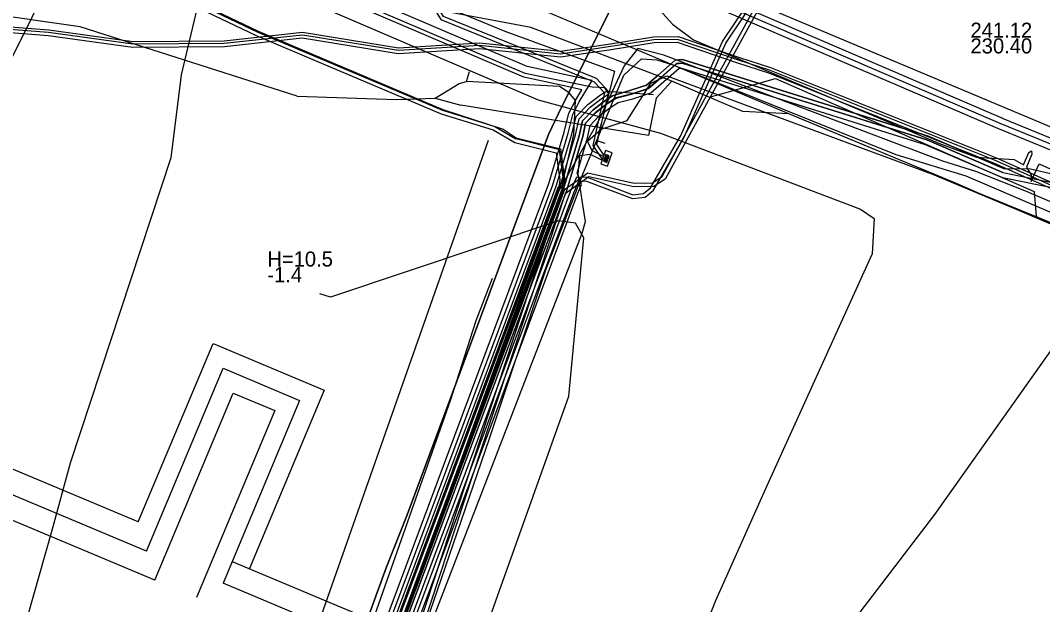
# Model space of a CAD drawing. Extents: x -596024 to -594475, y -1163820 to -1161957.
# Drawn here: x -594948.5 to -594894.3, y -1162166 to -1162135 of the extents above; entities that cross this region are included whole.
import ezdxf

# ---------------------------------------------------------------- set-up
doc = ezdxf.new("R2010")
doc.units = 0
for name, color, linetype in [('Vrstva 10', 7, 'Continuous'), ('Vrstva 12', 7, 'Continuous'), ('Vrstva 13', 7, 'Continuous'), ('Vrstva 19', 7, 'Continuous'), ('Vrstva 28', 7, 'Continuous'), ('Vrstva 29', 7, 'Continuous'), ('Vrstva 30', 7, 'Continuous'), ('Vrstva 32', 7, 'Continuous'), ('Vrstva 42', 7, 'Continuous'), ('Vrstva 43', 7, 'Continuous'), ('Vrstva 44', 7, 'Continuous'), ('Vrstva 55', 7, 'Continuous'), ('Vrstva 58', 7, 'Continuous'), ('Vrstva 9', 7, 'Continuous')]:
    doc.layers.add(name, color=color, linetype=linetype)

# ---------------------------------------------------------------- blocks, each defined once
blk = doc.blocks.new('NN620')
at = {"layer": 'Vrstva 28'}
for points in [[(0.752, 0.004), (-0.748, 0.004)], [(-0.748, 0.004), (-0.748, -0.746)], [(0.752, -0.746), (0.752, 0.004)], [(-0.748, -0.746), (0.752, -0.746)], [(0.368, -0.18), (-0.376, -0.18)], [(-0.376, -0.18), (-0.376, -0.558)], [(-0.376, -0.558), (0.368, -0.558)], [(0.321, -0.227), (-0.329, -0.227)], [(-0.329, -0.227), (-0.329, -0.51)], [(-0.329, -0.51), (0.321, -0.51)], [(0.274, -0.274), (-0.281, -0.274)], [(-0.281, -0.274), (-0.281, -0.463)], [(-0.281, -0.463), (0.274, -0.463)], [(0.227, -0.321), (-0.234, -0.321)], [(-0.234, -0.321), (-0.234, -0.416)], [(-0.234, -0.416), (0.227, -0.416)], [(-0.193, -0.369), (0.185, -0.369)], [(0.227, -0.416), (0.227, -0.321)], [(0.274, -0.463), (0.274, -0.274)], [(0.321, -0.51), (0.321, -0.227)], [(0.368, -0.558), (0.368, -0.18)]]:
    blk.add_lwpolyline(points, dxfattribs=at)

msp = doc.modelspace()

# ---------------------------------------------------------------- linework, layer by layer
at = {"layer": 'Vrstva 10'}
for p, q in [((-594919.937, -1162143.833), (-594940.567, -1162199.07)), ((-594919.582, -1162143.966), (-594919.937, -1162143.833)), ((-594940.222, -1162199.228), (-594919.582, -1162143.966))]:
    msp.add_line(p, q, dxfattribs=at)
for points in [[(-594940.233, -1162121.484), (-594916.901, -1162131.369), (-594896.381, -1162140.194)], [(-594896.619, -1162140.746), (-594917.137, -1162131.921), (-594940.467, -1162122.036)], [(-594896.386, -1162140.192), (-594890.529, -1162142.591), (-594841.464, -1162163.403), (-594840.002, -1162164.043)], [(-594840.243, -1162164.592), (-594841.702, -1162163.954), (-594890.76, -1162143.145), (-594896.614, -1162140.748)]]:
    msp.add_lwpolyline(points, dxfattribs=at)
at = {"layer": 'Vrstva 12'}
for points in [[(-594940.94, -1162120.86), (-594854.77, -1162157.03), (-594809.16, -1162176.45), (-594767.38, -1162194.31)], [(-594911.16, -1162139.42), (-594913.92, -1162138.24), (-594921.4, -1162135.39), (-594927.24, -1162134.29), (-594932.63, -1162132.4), (-594937.89, -1162129.44), (-594940.81, -1162128.13), (-594942.02, -1162127.63), (-594943.32, -1162126.88)], [(-594890.15, -1162147.05), (-594893.45, -1162145.88), (-594897.64, -1162144.17), (-594898.91, -1162143.62), (-594907.38, -1162140.1), (-594931.56, -1162129.92)], [(-594945.29, -1162135.36), (-594970.72, -1162131.69)], [(-594938.65, -1162132.45), (-594939.94, -1162137.9), (-594940.48, -1162142.29), (-594945.83, -1162158.49), (-594946.79, -1162162.06), (-594950.07, -1162173.52), (-594957.82, -1162196.23), (-594973.83, -1162243.01), (-594986.34, -1162280.9), (-594995.28, -1162307.97), (-595001.11, -1162334.64), (-595000.94, -1162335.11), (-594999.28, -1162352.34), (-594997.66, -1162363.83), (-594996.8, -1162372.69), (-594994.36, -1162396.57), (-594993.55, -1162422.69), (-594989.89, -1162471.94), (-594989.27, -1162484.26), (-594988.21, -1162493.1)], [(-594938.18, -1162132.1), (-594937.46, -1162132.16), (-594921, -1162139.23), (-594914.51, -1162140.99), (-594903.91, -1162145.02), (-594903.18, -1162145.52), (-594903.29, -1162147.39), (-594908.88, -1162159.69), (-594911.61, -1162165.81), (-594913.37, -1162170.27), (-594915.79, -1162175.82), (-594916.73, -1162178.42), (-594917.54, -1162180.59), (-594921.54, -1162194.47), (-594922.15, -1162196.85), (-594922.34, -1162197.5), (-594928.73, -1162215.2), (-594934.96, -1162232.34), (-594941.42, -1162249.91), (-594947.63, -1162267.23)], [(-594933.78, -1162139.03), (-594945.29, -1162135.36)], [(-594924.805, -1162138.245), (-594924.64, -1162137.73)], [(-594926.46, -1162139.13), (-594925.2, -1162138.36), (-594924.805, -1162138.245)], [(-594919.76, -1162143.9), (-594919.12, -1162141.06), (-594919.03, -1162139.26), (-594919.36, -1162138.86), (-594919.88, -1162138.52), (-594924.805, -1162138.245)], [(-594913.92, -1162138.24), (-594914.74, -1162139.13), (-594915.15, -1162141.12)], [(-594910.9, -1162138.8), (-594908.41, -1162138.1), (-594894.7, -1162144.09), (-594894.59, -1162145.41), (-594893.45, -1162145.88)], [(-594911.93, -1162139.09), (-594910.9, -1162138.8)], [(-594933.78, -1162139.03), (-594928.51, -1162139.2)], [(-594928.51, -1162139.2), (-594926.46, -1162139.13)], [(-594926.46, -1162139.13), (-594925.1, -1162139.5)], [(-594915.15, -1162141.12), (-594925.1, -1162139.5)], [(-594893.69, -1162145.86), (-594897.64, -1162144.17), (-594898.91, -1162143.62), (-594907.7, -1162139.97), (-594910.15, -1162139.85), (-594911.16, -1162139.42)]]:
    msp.add_lwpolyline(points, dxfattribs=at)
at = {"layer": 'Vrstva 13'}
msp.add_line((-594923.653, -1162141.377), (-594961.69, -1162249.37), dxfattribs=at)
at = {"layer": 'Vrstva 19'}
msp.add_lwpolyline([(-594950.84, -1162140.46), (-594949.16, -1162137.51), (-594942.54, -1162124.16), (-594936.31, -1162112.2), (-594935.78, -1162111.19)], dxfattribs=at)
at = {"layer": 'Vrstva 29'}
msp.add_line((-594856.116, -1162199.06), (-594937.718, -1162164.841), dxfattribs=at)
for points in [[(-594941.776, -1162163.139), (-594999.69, -1162138.853), (-595039.153, -1162134.53)], [(-594941.776, -1162163.139), (-594937.714, -1162153.456), (-594933.657, -1162155.157), (-594937.718, -1162164.841)]]:
    msp.add_lwpolyline(points, dxfattribs=at)
at = {"layer": 'Vrstva 30'}
msp.add_line((-594937.235, -1162163.688), (-594855.633, -1162197.907), dxfattribs=at)
for points in [[(-594942.214, -1162161.6), (-594999.374, -1162137.63), (-595040.011, -1162133.178)], [(-594941.337, -1162164.679), (-595000.006, -1162140.076), (-595038.295, -1162135.882)], [(-594942.214, -1162161.6), (-594938.249, -1162152.147), (-594932.348, -1162154.621), (-594936.312, -1162164.075)], [(-594941.337, -1162164.679), (-594937.179, -1162154.765), (-594934.966, -1162155.693), (-594939.124, -1162165.607)]]:
    msp.add_lwpolyline(points, dxfattribs=at)
at = {"layer": 'Vrstva 42'}
for points in [[(-595076.85, -1162071.09), (-595070.609, -1162071.252), (-595067.572, -1162072.08), (-595066.504, -1162072.834), (-595064.969, -1162072.729), (-595057.526, -1162075.848), (-595046.042, -1162082.224), (-595037.826, -1162086.437), (-595033.97, -1162088.19), (-595033.845, -1162088.227), (-595023.376, -1162092.878), (-595010.628, -1162097.806), (-594996.365, -1162102.687), (-594987.338, -1162105.952), (-594979.828, -1162109.103), (-594975.585, -1162110.428), (-594962.839, -1162116.145), (-594952.248, -1162121.006), (-594946.053, -1162123.832), (-594934.8, -1162128.336), (-594926.951, -1162132.009), (-594926.08, -1162134.217), (-594922.779, -1162135.588), (-594916.95, -1162137.709)], [(-594980.66, -1162108.582), (-594972.19, -1162112.242), (-594967.319, -1162114.362), (-594955.18, -1162119.492), (-594946.48, -1162123.302), (-594944.929, -1162123.972), (-594934.009, -1162128.492), (-594930.457, -1162130.039), (-594926.957, -1162132.269), (-594926.667, -1162132.85), (-594926.446, -1162134.504), (-594926.158, -1162134.97), (-594918.028, -1162138.264), (-594917.479, -1162138.859), (-594918.097, -1162141.64), (-594917.597, -1162142.398)], [(-594917.505, -1162142.173), (-594917.883, -1162141.6), (-594917.261, -1162138.801), (-594917.912, -1162138.096), (-594926.022, -1162134.81), (-594926.254, -1162134.436), (-594926.473, -1162132.79), (-594926.803, -1162132.131), (-594930.363, -1162129.861), (-594933.931, -1162128.308), (-594944.851, -1162123.788), (-594946.4, -1162123.118), (-594955.1, -1162119.308), (-594967.241, -1162114.178), (-594972.11, -1162112.058), (-594980.58, -1162108.398)], [(-595050.25, -1162124.49), (-595039.596, -1162125.409), (-595026.932, -1162127.038), (-595017.39, -1162128.669), (-595009.367, -1162129.499), (-594997.514, -1162130.979), (-594984.744, -1162131.839), (-594968.747, -1162133.829), (-594955.433, -1162135.149), (-594946.986, -1162135.809), (-594942.51, -1162136.43), (-594937.641, -1162136.39), (-594933.514, -1162135.941), (-594928.427, -1162136.761), (-594924.123, -1162136.5), (-594919.817, -1162136.951), (-594917.127, -1162136.548), (-594914.857, -1162136.19), (-594913.634, -1162136.17)], [(-594841.6, -1162165.96), (-594861.847, -1162157.553), (-594879.336, -1162150.176), (-594896.797, -1162142.418), (-594908.73, -1162137.65), (-594910.38, -1162137.12), (-594913.61, -1162136.02), (-594914.87, -1162136.04), (-594917.15, -1162136.4), (-594919.82, -1162136.8), (-594924.12, -1162136.35), (-594928.42, -1162136.61), (-594933.51, -1162135.79), (-594937.65, -1162136.24), (-594942.5, -1162136.28), (-594946.97, -1162135.66), (-594955.42, -1162135), (-594968.73, -1162133.68), (-594984.73, -1162131.69)], [(-594984.716, -1162131.541), (-594968.713, -1162133.531), (-594955.407, -1162134.851), (-594946.954, -1162135.511), (-594942.49, -1162136.13), (-594937.659, -1162136.09), (-594933.506, -1162135.639), (-594928.413, -1162136.459), (-594924.117, -1162136.2), (-594919.823, -1162136.649), (-594917.173, -1162136.252), (-594914.883, -1162135.89), (-594913.586, -1162135.87), (-594910.333, -1162136.978), (-594908.679, -1162137.509), (-594896.739, -1162142.28), (-594879.276, -1162150.038), (-594861.789, -1162157.415), (-594841.589, -1162165.801)], [(-594913.634, -1162136.17), (-594910.427, -1162137.262), (-594908.781, -1162137.791), (-594896.855, -1162142.556), (-594879.396, -1162150.314), (-594861.905, -1162157.691), (-594841.61, -1162166.119), (-594824.059, -1162173.618), (-594805.561, -1162181.567), (-594805, -1162180.3)], [(-594937.107, -1162195.119), (-594934.887, -1162188.459), (-594930.947, -1162177.769), (-594927.747, -1162169.249), (-594926.547, -1162165.839), (-594923.577, -1162157.179), (-594920.597, -1162148.239), (-594918.637, -1162143.169), (-594916.467, -1162137.919), (-594915.517, -1162137.059), (-594914.707, -1162137.099), (-594913.807, -1162137.389), (-594902.037, -1162142.129), (-594900.637, -1162142.549), (-594898.327, -1162143.259), (-594886.337, -1162148.389), (-594878.867, -1162151.329), (-594865.957, -1162156.909), (-594855.387, -1162161.629), (-594853.437, -1162162.409), (-594846.747, -1162164.939), (-594845.647, -1162165.599)], [(-594916.95, -1162137.709), (-594917.885, -1162141.384), (-594917.467, -1162141.526)], [(-594918.39, -1162141.42), (-594917.656, -1162140.779), (-594916.29, -1162140.323), (-594915.023, -1162138.336), (-594914.181, -1162137.948), (-594900.083, -1162143.168), (-594886.163, -1162149.001), (-594869.698, -1162155.547), (-594853.08, -1162162.966), (-594846.011, -1162165.912), (-594834.439, -1162170.677), (-594821.566, -1162176.03), (-594821.941, -1162177.042), (-594821.122, -1162176.345), (-594809.258, -1162181.472), (-594797.324, -1162187.054), (-594800.93, -1162194.949), (-594800.802, -1162195.021)], [(-594917.53, -1162142.236), (-594918.135, -1162141.93), (-594918.39, -1162141.42)], [(-594958.127, -1162262.266), (-594959.535, -1162261.439), (-594957.574, -1162255.697), (-594953.584, -1162242.328), (-594946.169, -1162221.585), (-594940.703, -1162204.889), (-594939.204, -1162199.363), (-594918.663, -1162146.295), (-594918.491, -1162145.679), (-594918.643, -1162144.786), (-594918.89, -1162143.172), (-594918.8, -1162142.17)], [(-594918.8, -1162142.17), (-594918.238, -1162142.102), (-594917.605, -1162142.427)]]:
    msp.add_lwpolyline(points, dxfattribs=at)
at = {"layer": 'Vrstva 44'}
for points in [[(-595066.105, -1162080.68), (-595062.648, -1162081.161), (-595060.545, -1162081.694), (-595054.166, -1162084.398), (-595048.287, -1162087.117), (-595041.419, -1162089.957), (-595034.638, -1162092.727), (-595027.287, -1162095.887), (-595020.408, -1162098.857), (-595012.508, -1162102.227), (-595006.858, -1162104.577), (-595000.518, -1162107.237), (-594990.789, -1162111.317), (-594975.868, -1162117.447), (-594966.828, -1162121.287), (-594957.228, -1162125.287), (-594950.556, -1162128.178), (-594946.028, -1162130.341), (-594943.328, -1162132.061), (-594935.876, -1162135.638), (-594926.073, -1162139.775), (-594923.737, -1162140.504), (-594923.306, -1162140.637), (-594922.193, -1162141.292)], [(-595048.367, -1162087.301), (-595041.495, -1162090.141), (-595034.716, -1162092.911), (-595027.367, -1162096.071), (-595020.486, -1162099.041), (-595012.586, -1162102.411), (-595006.936, -1162104.761), (-595000.596, -1162107.421), (-594990.865, -1162111.501), (-594975.946, -1162117.631), (-594966.906, -1162121.471), (-594957.306, -1162125.471), (-594950.638, -1162128.36), (-594946.126, -1162130.517), (-594943.426, -1162132.237), (-594935.958, -1162135.82), (-594926.141, -1162139.963), (-594923.797, -1162140.694)], [(-594897.711, -1162113.224), (-594899.327, -1162116.203), (-594914.275, -1162143.43), (-594914.877, -1162143.814), (-594915.93, -1162143.835), (-594918.319, -1162143.304), (-594919.57, -1162144.214), (-594928.47, -1162171.229), (-594938.587, -1162197.497), (-594939.94, -1162199.983), (-594948.355, -1162223.097), (-594959.108, -1162256.412), (-594959.244, -1162256.859), (-594960.697, -1162257.338), (-594962.509, -1162256.765), (-594967.966, -1162254.906), (-594973.009, -1162253.137), (-594974.955, -1162249.758), (-594981.381, -1162245.435), (-594988.082, -1162242.336), (-594992.7, -1162240.377), (-594999.092, -1162238.351), (-595000.799, -1162237.338), (-595000.448, -1162236.382)], [(-594988.666, -1162240.447), (-594988.908, -1162241.782), (-594987.998, -1162242.153), (-594981.353, -1162245.28), (-594974.83, -1162249.699), (-594972.891, -1162253.002), (-594967.908, -1162254.744), (-594962.542, -1162256.591), (-594960.679, -1162257.077), (-594959.389, -1162256.632), (-594959.298, -1162256.35), (-594948.545, -1162223.033), (-594940.126, -1162199.911), (-594938.856, -1162197.362), (-594928.658, -1162171.161), (-594919.74, -1162144.09), (-594918.363, -1162143.09), (-594915.91, -1162143.635), (-594914.937, -1162143.616), (-594914.425, -1162143.288), (-594899.507, -1162116.113), (-594898.072, -1162113.187)], [(-594846.169, -1162165.001), (-594853.363, -1162161.962), (-594857.354, -1162160.035), (-594858.446, -1162159.592), (-594871.926, -1162154.019), (-594895.105, -1162144.081), (-594897.792, -1162143.031), (-594899.536, -1162142.474), (-594908.933, -1162138.923), (-594914.33, -1162136.854), (-594915.725, -1162136.497), (-594916.45, -1162137.416), (-594917.826, -1162140.371), (-594919.903, -1162144.04), (-594939.241, -1162197.227), (-594938.236, -1162199.894)], [(-594923.797, -1162140.694), (-594923.388, -1162140.821), (-594922.241, -1162141.486), (-594920.047, -1162142.03), (-594919.858, -1162143.46), (-594919.905, -1162143.865), (-594926.841, -1162162.484), (-594933.661, -1162180.834), (-594940.621, -1162199.465), (-594946.442, -1162216.657), (-594950.872, -1162229.747), (-594955.304, -1162242.843), (-594955.443, -1162243.548), (-594955.998, -1162244.737)], [(-594940.433, -1162199.533), (-594933.473, -1162180.904), (-594926.653, -1162162.554), (-594919.709, -1162143.913), (-594919.656, -1162143.458), (-594919.867, -1162141.868), (-594922.193, -1162141.292)]]:
    msp.add_lwpolyline(points, dxfattribs=at)
at = {"layer": 'Vrstva 55'}
for points in [[(-594967.54, -1162111.09), (-594967.419, -1162111.217), (-594967.07, -1162111.74), (-594965.97, -1162112.52), (-594930.14, -1162127.63), (-594928.12, -1162128.31), (-594927.13, -1162128.26), (-594926.8, -1162128.76), (-594924.95, -1162129.72), (-594914.91, -1162134.08), (-594913.88, -1162135.21), (-594912.76, -1162136.04), (-594899.72, -1162141.53), (-594897.75, -1162142.26), (-594895.75, -1162142.38), (-594895.26, -1162142.67), (-594894.98, -1162142.02), (-594894.83, -1162141.93), (-594894.811, -1162142.104), (-594895.1, -1162142.8), (-594894.85, -1162143.2), (-594894.85, -1162143.56)], [(-594894.85, -1162143.56), (-594894.438, -1162142.612), (-594883.55, -1162147.55), (-594787.08, -1162187.61)], [(-594907.427, -1162170.962), (-594899.967, -1162161.198), (-594890.461, -1162147.786)]]:
    msp.add_lwpolyline(points, dxfattribs=at)
at = {"layer": 'Vrstva 58'}
for points in [[(-594919.368, -1162137.929), (-594921.585, -1162137.464), (-594934.55, -1162131.91), (-594952.103, -1162124.364), (-594967.606, -1162119.083), (-595001.852, -1162105.029), (-595031.838, -1162092.02), (-595054.841, -1162081.989)], [(-594941.094, -1162198.987), (-594920.43, -1162143.658), (-594919.617, -1162140.938), (-594919.37, -1162139.932), (-594919.014, -1162139.223), (-594918.681, -1162138.689), (-594919.617, -1162138.478), (-594921.764, -1162138.03), (-594934.783, -1162132.453), (-594952.315, -1162124.916), (-594967.814, -1162119.636), (-595002.082, -1162105.573), (-595032.074, -1162092.561), (-595055.072, -1162082.532)], [(-594917.46, -1162138.59), (-594918.145, -1162138.56), (-594921.7, -1162137.83), (-594934.7, -1162132.26), (-594952.24, -1162124.72), (-594967.74, -1162119.44), (-595002, -1162105.38), (-595031.99, -1162092.37), (-595054.99, -1162082.34)], [(-594917.46, -1162138.59), (-594918.145, -1162138.56), (-594921.7, -1162137.83), (-594934.7, -1162132.26), (-594952.24, -1162124.72), (-594967.74, -1162119.44), (-595002, -1162105.38), (-595031.99, -1162092.37), (-595054.99, -1162082.34)], [(-595041.397, -1162089.909), (-595034.617, -1162092.679), (-595027.267, -1162095.839), (-595020.387, -1162098.809), (-595012.487, -1162102.179), (-595006.837, -1162104.529), (-595000.497, -1162107.189), (-594990.767, -1162111.269), (-594975.847, -1162117.399), (-594966.807, -1162121.239), (-594957.207, -1162125.239), (-594950.537, -1162128.129), (-594946.007, -1162130.299), (-594943.307, -1162132.019), (-594935.857, -1162135.589), (-594926.057, -1162139.729), (-594922.857, -1162140.779), (-594922.177, -1162141.239), (-594919.817, -1162141.829), (-594919.607, -1162143.459), (-594919.657, -1162143.929), (-594926.607, -1162162.569), (-594933.427, -1162180.919), (-594940.387, -1162199.549)], [(-594939.981, -1162199.469), (-594919.291, -1162144.075), (-594918.955, -1162143.309), (-594918.4, -1162143.331), (-594915.977, -1162144.258), (-594915.412, -1162144.194), (-594915.048, -1162143.885), (-594913.459, -1162141.144), (-594911.218, -1162136.132), (-594909.264, -1162133.195), (-594904.464, -1162125.806), (-594902.965, -1162123.407), (-594901.238, -1162120.682), (-594900.073, -1162118.203), (-594899.805, -1162117.369), (-594898.1, -1162112.89), (-594898.39, -1162112.21), (-594898.67, -1162111.91)], [(-594939.797, -1162199.549), (-594919.104, -1162144.145), (-594918.846, -1162143.509), (-594918.44, -1162143.529), (-594916.003, -1162144.462), (-594915.328, -1162144.386), (-594914.892, -1162144.015), (-594913.281, -1162141.236), (-594911.042, -1162136.228), (-594909.096, -1162133.305), (-594904.296, -1162125.914), (-594902.795, -1162123.513), (-594901.062, -1162120.778), (-594899.887, -1162118.277), (-594899.615, -1162117.431), (-594897.23, -1162114.29)], [(-594881.54, -1162134.66), (-594886.2, -1162132.57), (-594908.87, -1162123.34), (-594910.38, -1162122.75), (-594911.37, -1162122.84), (-594919.74, -1162139.57), (-594920.46, -1162141.06), (-594927.96, -1162161.23), (-594929.06, -1162164.03), (-594931.14, -1162169.7), (-594932.08, -1162172.59), (-594942.61, -1162200.07)], [(-594942.61, -1162200.07), (-594932.08, -1162172.59), (-594931.14, -1162169.7), (-594929.06, -1162164.03), (-594927.96, -1162161.23), (-594920.46, -1162141.06), (-594919.74, -1162139.57), (-594911.37, -1162122.84), (-594910.38, -1162122.75), (-594908.87, -1162123.34), (-594886.2, -1162132.57), (-594881.54, -1162134.66), (-594872.81, -1162138.34), (-594871.48, -1162138.9), (-594855.8, -1162145.62), (-594837.62, -1162153.37)], [(-594837.566, -1162146.596), (-594857.422, -1162138.112), (-594869.918, -1162132.659), (-594883.928, -1162127.139), (-594885.518, -1162126.885), (-594888.661, -1162132.624), (-594893.146, -1162143.052), (-594893.665, -1162143.184), (-594894.887, -1162142.9), (-594896.271, -1162142.888)], [(-594896.359, -1162143.07), (-594893.66, -1162143.62), (-594892.84, -1162143.41), (-594888.28, -1162132.81), (-594885.29, -1162127.35), (-594884.04, -1162127.55), (-594870.08, -1162133.05), (-594857.59, -1162138.5), (-594837.72, -1162146.99)], [(-594896.359, -1162143.07), (-594893.66, -1162143.62), (-594892.84, -1162143.41), (-594888.28, -1162132.81), (-594885.29, -1162127.35), (-594884.04, -1162127.55), (-594870.08, -1162133.05), (-594857.59, -1162138.5), (-594837.72, -1162146.99)], [(-594939.61, -1162199.63), (-594918.915, -1162144.219), (-594918.713, -1162143.717), (-594918.94, -1162143.104), (-594918.381, -1162141.232), (-594918.252, -1162140.579), (-594917.796, -1162140.109), (-594917.204, -1162139.652), (-594916.768, -1162139.367), (-594915.984, -1162139.169), (-594915.031, -1162138.859), (-594914.333, -1162138.259), (-594913.549, -1162137.557), (-594913.399, -1162137.543), (-594900.475, -1162141.587), (-594896.373, -1162143.339), (-594893.653, -1162143.892), (-594892.648, -1162143.635), (-594888.041, -1162132.926), (-594885.147, -1162127.641), (-594884.11, -1162127.807), (-594870.182, -1162133.295), (-594857.695, -1162138.744), (-594837.816, -1162147.237)], [(-594940.348, -1162199.31), (-594919.666, -1162143.935), (-594918.827, -1162141.126), (-594918.657, -1162140.338), (-594918.103, -1162139.765), (-594917.47, -1162139.278), (-594917.067, -1162139.015), (-594916.084, -1162138.72), (-594915.26, -1162138.451), (-594914.636, -1162137.915), (-594913.742, -1162137.113), (-594913.349, -1162137.079), (-594900.315, -1162141.156), (-594896.271, -1162142.888)], [(-594896.271, -1162142.888), (-594900.315, -1162141.156), (-594913.349, -1162137.079), (-594913.742, -1162137.113), (-594914.636, -1162137.915), (-594915.26, -1162138.451), (-594916.084, -1162138.72), (-594917.067, -1162139.015), (-594917.47, -1162139.278), (-594918.103, -1162139.765), (-594918.657, -1162140.338), (-594918.827, -1162141.126), (-594919.666, -1162143.935), (-594940.348, -1162199.31)], [(-594896.359, -1162143.07), (-594900.395, -1162141.342), (-594913.381, -1162137.279), (-594913.668, -1162137.305), (-594914.514, -1162138.063), (-594915.17, -1162138.627), (-594916.066, -1162138.918), (-594916.883, -1162139.125), (-594917.364, -1162139.439), (-594917.979, -1162139.913), (-594918.501, -1162140.452), (-594918.642, -1162141.168), (-594919.489, -1162144.003), (-594940.174, -1162199.388)], [(-594940.164, -1162199.39), (-594919.479, -1162144.005), (-594918.632, -1162141.17), (-594918.491, -1162140.454), (-594917.969, -1162139.915), (-594917.354, -1162139.441), (-594916.873, -1162139.127), (-594916.056, -1162138.92), (-594915.16, -1162138.629), (-594914.504, -1162138.065), (-594913.658, -1162137.307), (-594913.371, -1162137.281), (-594900.385, -1162141.344), (-594896.349, -1162143.072)], [(-594977.104, -1162237.777), (-594972.449, -1162239.243), (-594971.305, -1162239.645), (-594970.538, -1162239.875), (-594968.928, -1162240.33), (-594963.762, -1162241.935), (-594958.326, -1162243.856), (-594957.707, -1162243.901), (-594957.133, -1162243.935), (-594956.515, -1162243.74), (-594956.11, -1162243.341), (-594955.729, -1162242.675), (-594941.554, -1162200.389), (-594940.899, -1162199.071), (-594920.229, -1162143.725), (-594919.413, -1162140.994), (-594919.17, -1162140.006), (-594918.829, -1162139.326), (-594918.145, -1162138.205), (-594919.368, -1162137.929)], [(-594977.237, -1162238.155), (-594972.575, -1162239.623), (-594971.429, -1162240.025), (-594970.65, -1162240.259), (-594969.042, -1162240.714), (-594963.888, -1162242.315), (-594958.409, -1162244.251), (-594957.733, -1162244.3), (-594957.083, -1162244.339), (-594956.303, -1162244.092), (-594955.79, -1162243.588), (-594955.362, -1162242.839), (-594941.183, -1162200.542), (-594940.532, -1162199.23), (-594919.854, -1162143.865), (-594919.022, -1162141.082), (-594918.823, -1162140.222), (-594918.237, -1162139.615), (-594917.586, -1162139.114), (-594917.261, -1162138.903), (-594917.46, -1162138.59)], [(-594977.17, -1162237.966), (-594972.512, -1162239.433), (-594971.367, -1162239.835), (-594970.594, -1162240.067), (-594968.985, -1162240.522), (-594963.825, -1162242.125), (-594958.368, -1162244.053), (-594957.72, -1162244.1), (-594957.108, -1162244.137), (-594956.409, -1162243.916), (-594955.95, -1162243.465), (-594955.545, -1162242.757), (-594941.368, -1162200.465), (-594940.716, -1162199.15), (-594920.041, -1162143.795), (-594919.218, -1162141.038), (-594918.989, -1162140.106), (-594918.371, -1162139.465), (-594917.702, -1162138.951), (-594917.455, -1162138.791), (-594917.04, -1162138.79), (-594914.888, -1162138.949)], [(-594919.854, -1162143.865), (-594919.022, -1162141.082), (-594918.823, -1162140.222), (-594918.237, -1162139.615), (-594917.586, -1162139.114), (-594917.261, -1162138.903), (-594917.46, -1162138.59)], [(-594977.237, -1162238.155), (-594972.575, -1162239.623), (-594971.429, -1162240.025), (-594970.65, -1162240.259), (-594969.042, -1162240.714), (-594963.888, -1162242.315), (-594958.409, -1162244.251), (-594957.733, -1162244.3), (-594957.083, -1162244.339), (-594956.303, -1162244.092), (-594955.79, -1162243.588), (-594955.362, -1162242.839), (-594941.183, -1162200.542), (-594940.532, -1162199.23), (-594919.854, -1162143.865)], [(-594977.323, -1162238.502), (-594953.106, -1162246.109), (-594952.086, -1162246.06), (-594951.616, -1162245.889), (-594951.076, -1162245.359), (-594950.636, -1162244.589), (-594936.456, -1162202.288), (-594935.76, -1162200.858), (-594919.383, -1162154.938), (-594918.589, -1162146.546), (-594919.016, -1162145.753), (-594919.93, -1162145.631), (-594932.014, -1162149.685), (-594932.576, -1162149.499)]]:
    msp.add_lwpolyline(points, dxfattribs=at)
at = {"layer": 'Vrstva 9'}
for p, q in [((-594924.288, -1162150.915), (-594923.434, -1162148.674)), ((-594925.642, -1162155.114), (-594924.288, -1162150.915))]:
    msp.add_line(p, q, dxfattribs=at)
for points in [[(-594896.5, -1162140.47), (-594917.019, -1162131.645), (-594940.35, -1162121.76)], [(-594840.122, -1162164.318), (-594841.583, -1162163.678), (-594890.644, -1162142.868), (-594896.5, -1162140.47)], [(-594939.45, -1162195.364), (-594937.626, -1162189.112), (-594925.642, -1162155.114)]]:
    msp.add_lwpolyline(points, dxfattribs=at)

# ---------------------------------------------------------------- block references
at = {"layer": 'Vrstva 43', "xscale": 0.5, "yscale": 0.5, "rotation": 71}
msp.add_blockref('NN620', (-594917.56, -1162142.27), dxfattribs=at)

# ---------------------------------------------------------------- texts
at = {"layer": 'Vrstva 12'}
for s, p in [('241.12', (-594898.074, -1162135.934)), ('230.40', (-594898.074, -1162136.766))]:
    msp.add_text(s, height=0.8, dxfattribs=at).set_placement(p)
at = {"layer": 'Vrstva 32'}
for s, p in [('H=10.5  ', (-594935.37, -1162148.061)), ('-1.4', (-594935.37, -1162148.893))]:
    msp.add_text(s, height=0.8, dxfattribs=at).set_placement(p)

doc.saveas('drawing.dxf')
